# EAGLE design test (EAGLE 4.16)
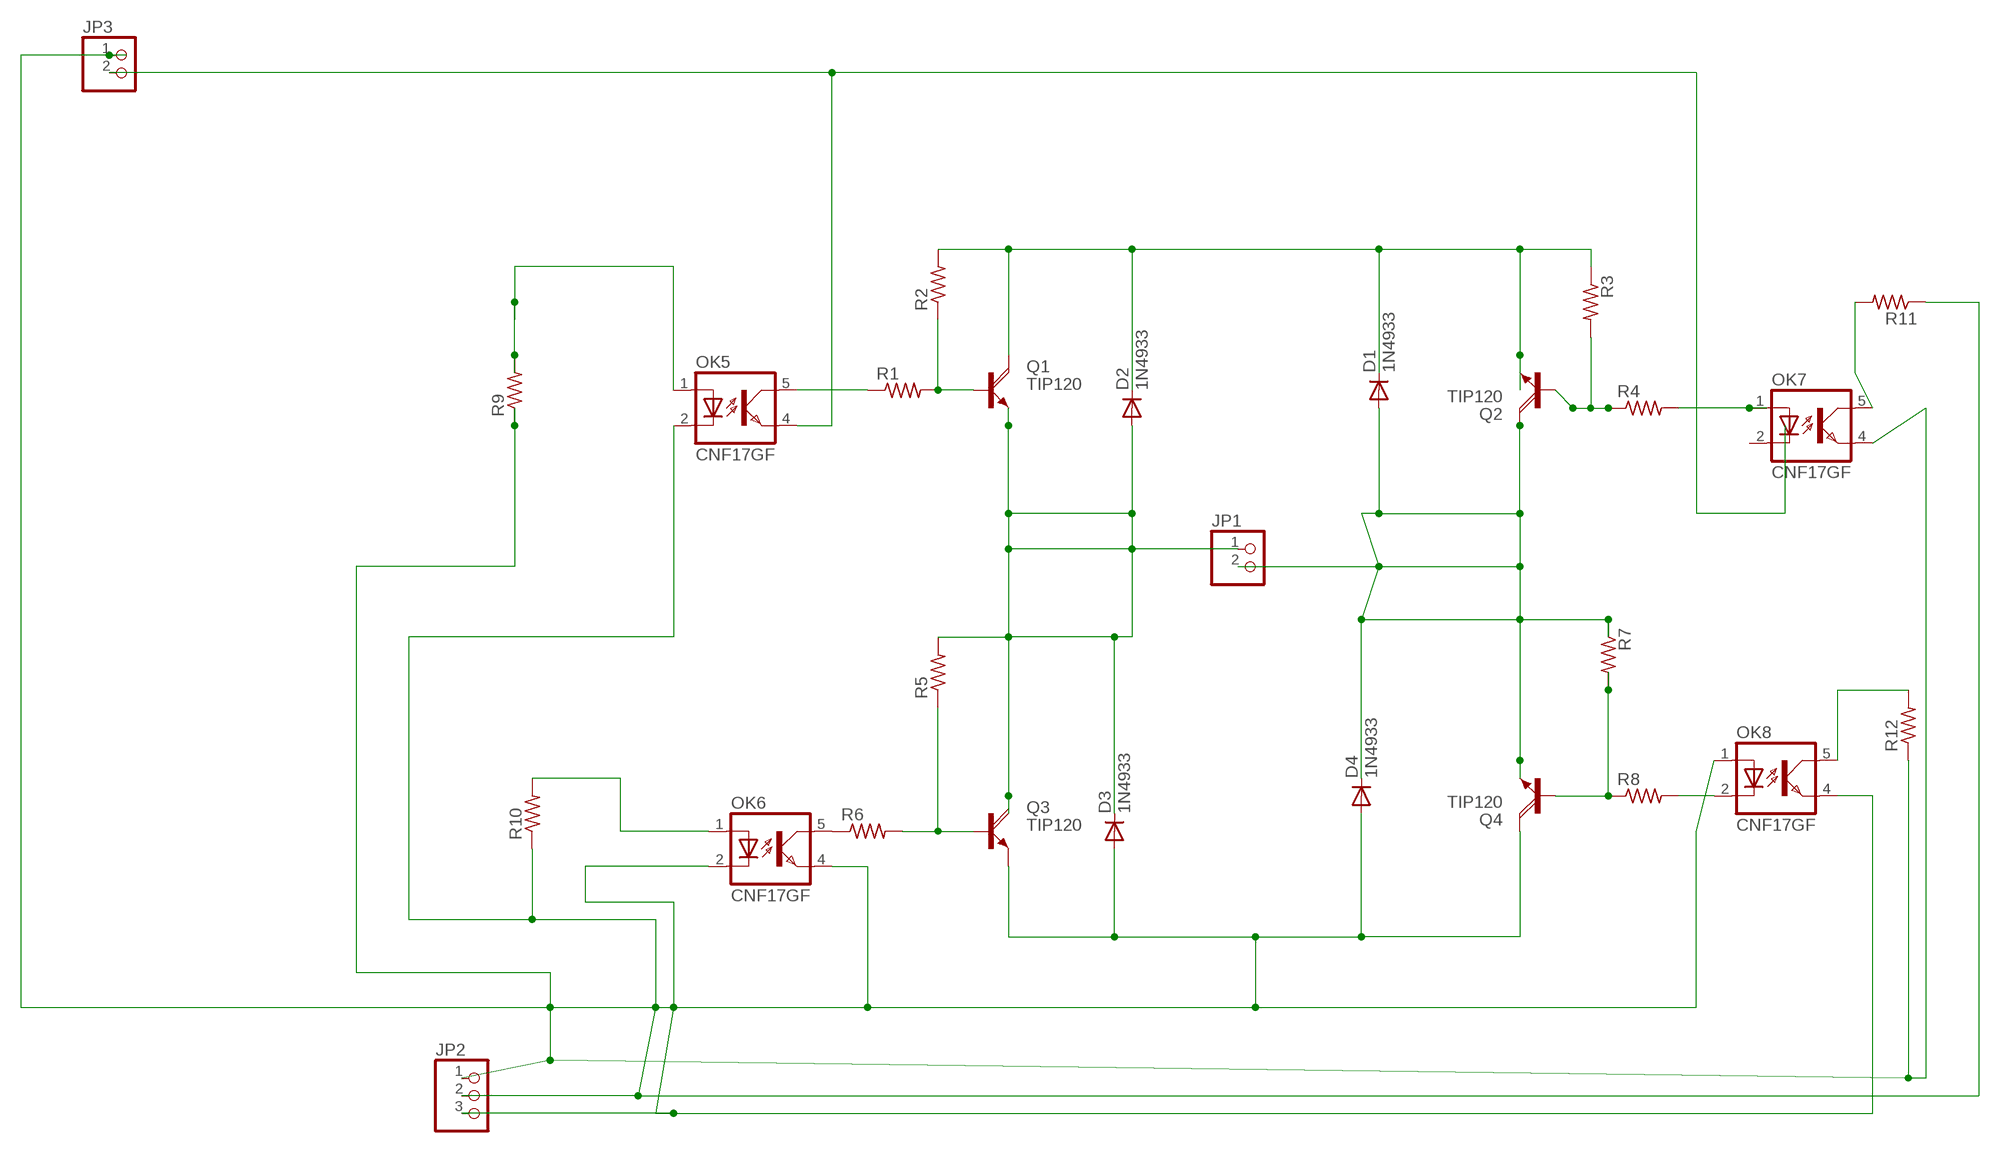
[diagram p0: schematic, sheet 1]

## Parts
D1  1N4933  [DO41-10]
D2  1N4933  [DO41-10]
D3  1N4933  [DO41-10]
D4  1N4933  [DO41-10]
JP1  PINHD-1X2  [1X02]
JP2  PINHD-1X3  [1X03]
JP3  PINHD-1X2  [1X02]
OK5  CNF17GF  [DIL06B]
OK6  CNF17GF  [DIL06B]
OK7  CNF17GF  [DIL06B]
OK8  CNF17GF  [DIL06B]
Q1  TIP120  [TO220AH]
Q2  TIP120  [TO220AH]
Q3  TIP120  [TO220AH]
Q4  TIP120  [TO220AH]
R1  R-US_0204/2V  [0204V]
R2  R-US_0204/2V  [0204V]
R3  R-US_0204/2V  [0204V]
R4  R-US_0204/2V  [0204V]
R5  R-US_0204/2V  [0204V]
R6  R-US_0204/2V  [0204V]
R7  R-US_0204/2V  [0204V]
R8  R-US_0204/2V  [0204V]
R9  R-US_0204/2V  [0204V]
R10  R-US_0204/2V  [0204V]
R11  R-US_0204/2V  [0204V]
R12  R-US_0204/2V  [0204V]

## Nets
N$1: OK5.5(COL) R1.1
N$2: Q1.B R1.2 R2.1
N$3: OK6.5(COL) R6.1
N$4: D1.C D2.C Q1.C Q2.E R2.2 R3.1
N$5: D2.A D3.C JP1.1 Q1.E Q3.C R5.2
N$6: D1.A D4.C JP1.2 Q2.C Q4.E R7.1
N$7: Q2.B R3.2 R4.1
N$8: Q3.B R5.1 R6.2
N$9: OK5.1(A) R9.2
N$10: D3.A D4.A JP2.1 JP2.2 JP2.3 JP3.1 OK5.2(C) OK6.2(C) OK6.4(EMIT) OK7.4(EMIT) OK8.1(A) OK8.4(EMIT) Q3.E Q4.C R9.1 R10.1 R11.1 R12.1
N$11: OK6.1(A) R10.2
N$12: OK7.5(COL) R11.2
N$13: Q4.B R7.2 R8.1
N$14: OK7.1(A) R4.2
N$15: OK8.2(C) R8.2
N$17: JP3.2 OK5.4(EMIT)
N$18: OK8.5(COL) R12.2
Unconnected: OK7.2(C)

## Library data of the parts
D1-D4 = diode:1N4933: DIODE
JP1 JP3 = pinhead:PINHD-1X2: PIN HEADER
JP2 = pinhead:PINHD-1X3: PIN HEADER
OK5-OK8 = optocoupler:CNF17GF: HEWLETT PACKARD OPTO COUPLER
Q1-Q4 = transistor-power:TIP120: NPN DARLINGTON TRANSISTOR
R1-R12 = rcl:R-US_: RESISTOR, American symbol

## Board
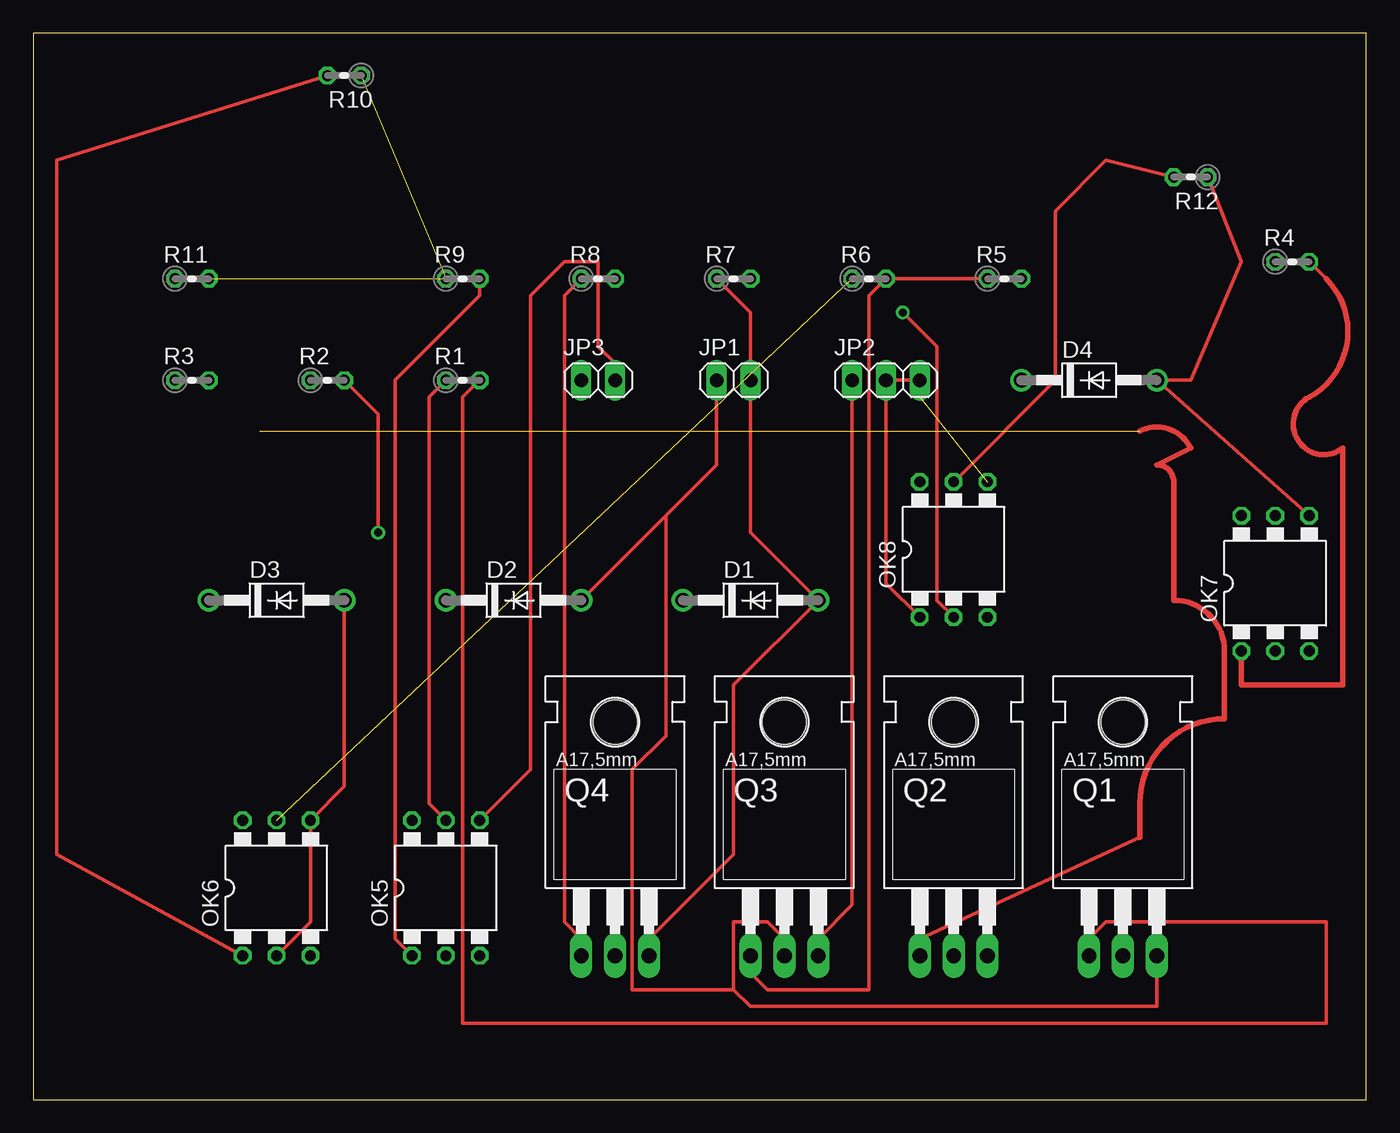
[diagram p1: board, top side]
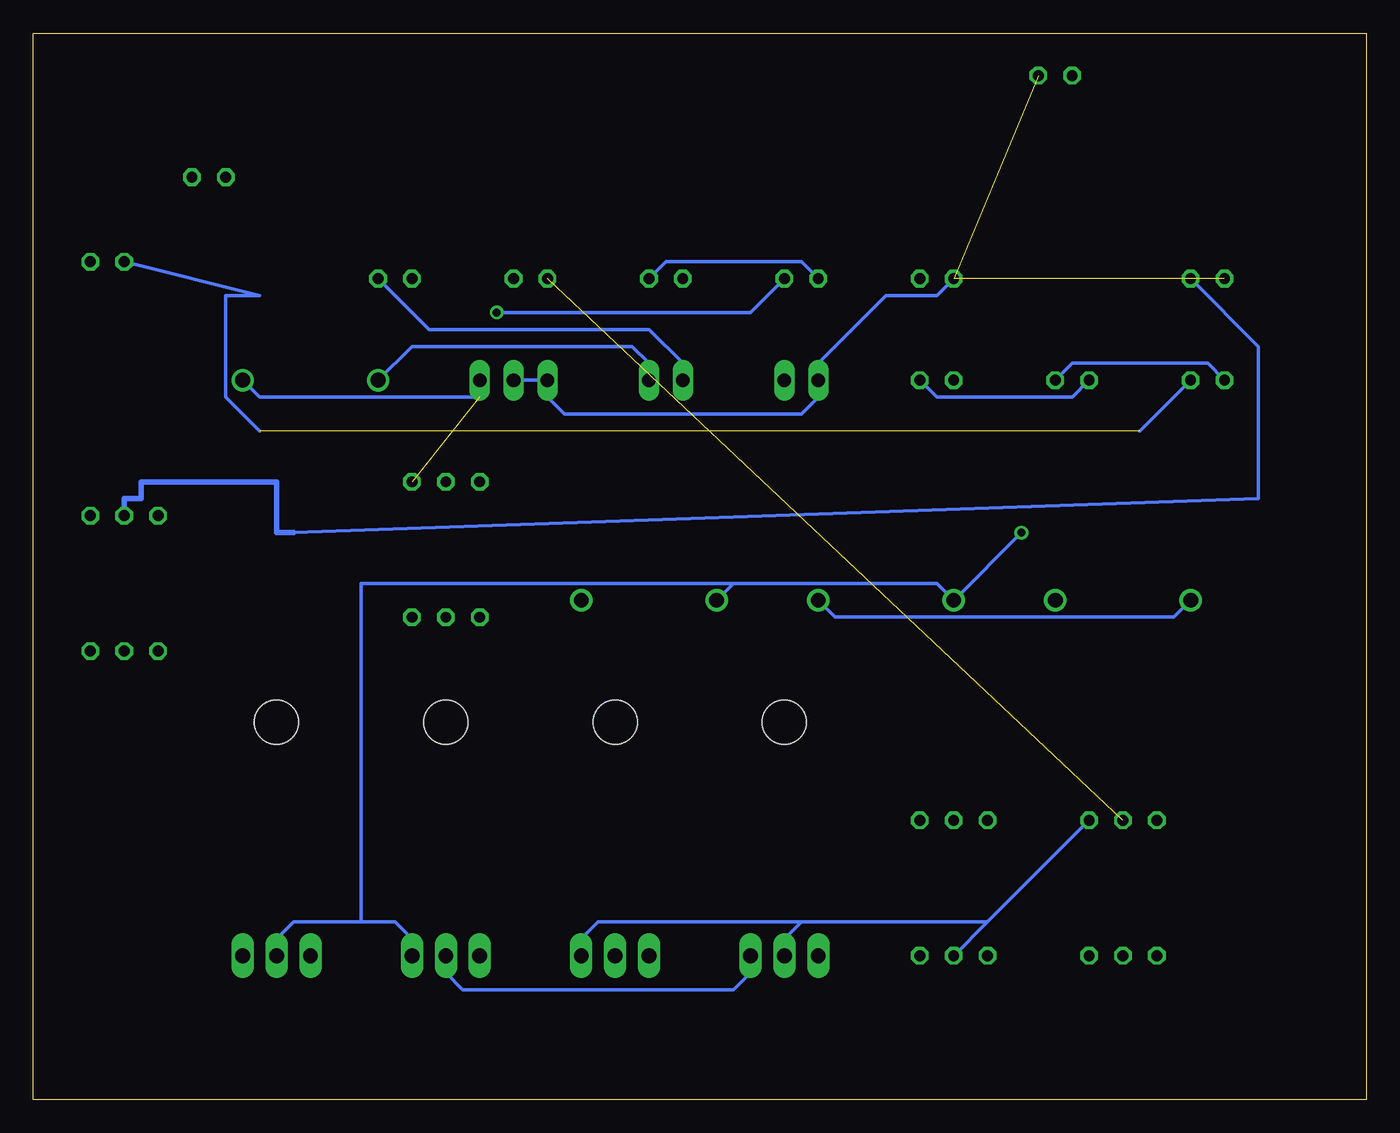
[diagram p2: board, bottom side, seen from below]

Size 100 x 80 mm. Coordinates in mm from the lower left corner, seen from the top.
Outline: 0,0 100,0 100,80 0,80 0,0
Copper layers (1*16): Top 0.035mm / dielectric 1.5mm / Bottom 0.035mm
Design rules "default": minimum track width 10mil, minimum drill 24mil, track to track 8mil, track to pad 8mil, pad to pad 8mil, via to via 8mil, smd to smd 8mil, copper to edge 40mil, drill to drill 8mil, minimum pad ring 10mil, minimum via ring 8mil, stop-mask expansion 4mil, vias tented up to drill 0mil, thermal gap 10mil

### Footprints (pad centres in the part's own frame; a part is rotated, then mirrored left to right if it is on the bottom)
DO41-10 = drill 1.118 round: A 5.08,0; C -5.08,0
1X02 = drill 1.016 long: 1 -1.27,0; 2 1.27,0
1X03 = drill 1.016 long: 1 -2.54,0; 2 0,0; 3 2.54,0
DIL06B = drill 0.813 octagon: 1 -2.54,-5.08; 2 0,-5.08; 3 2.54,-5.08; 4 2.54,5.08; 5 0,5.08; 6 -2.54,5.08
TO220AH = drill 1.118 long: B -2.54,-6.35; C 0,-6.35; E 2.54,-6.35 | hole 3.302: 0,11.176
0204V = drill 0.813 octagon: 1 -1.27,0; 2 1.27,0

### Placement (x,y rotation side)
D1  53.81,37.46 0 top
D2  36.03,37.46 0 top
D3  18.25,37.46 0 top
D4  79.21,53.97 0 top
JP1  52.54,53.97 0 top
JP2  63.97,53.97 0 top
JP3  42.38,53.97 0 top
OK5  30.95,15.87 0 top
OK6  18.25,15.87 0 top
OK7  93.18,38.73 0 top
OK8  69.05,41.27 0 top
Q1  81.75,17.14 0 top
Q2  69.05,17.14 0 top
Q3  56.35,17.14 0 top
Q4  43.65,17.14 0 top
R1  32.22,53.97 0 top
R2  22.06,53.97 0 top
R3  11.9,53.97 0 top
R4  94.45,62.86 0 top
R5  72.86,61.59 0 top
R6  62.7,61.59 0 top
R7  52.54,61.59 0 top
R8  42.38,61.59 0 top
R9  32.22,61.59 0 top
R10  23.33,76.83 180 top
R11  11.9,61.59 0 top
R12  86.83,69.21 180 top

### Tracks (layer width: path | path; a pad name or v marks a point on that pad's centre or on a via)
N$1
  Top 0.254: OK5.5 29.68,22.22 29.68,52.7 R1.1
N$2
  Top 0.254: R1.2 32.22,52.7 32.22,5.71 96.99,5.71 96.99,13.33 80.48,13.33 79.21,12.06 Q1.B
  Bottom 0.254: R2.1 22.06,52.7 32.22,52.7 R1.2
N$3  (1 unrouted)
N$4  (via drill 0.61)
  Top 0.254: R2.2 25.87,51.43 v25.87,42.54
  Bottom 0.254: R3.1 11.9,55.24 22.06,55.24 R2.2 | 75.4,13.33 80.48,13.33 81.75,12.06 Q1.C | 75.4,13.33 72.86,13.33 71.59,12.06 Q2.E | 47.46,38.73 32.22,38.73 D2.C v25.87,42.54 | 47.46,38.73 D1.C | 75.4,13.33 75.4,38.73 47.46,38.73
N$5
  Top 0.254: 52.54,8.25 52.54,13.33 55.08,13.33 56.35,12.06 Q3.C | 52.54,8.25 53.81,6.98 84.29,6.98 Q1.E | 47.46,43.81 51.27,47.62 JP1.1 | D2.A 47.46,43.81 | 52.54,8.25 44.92,8.25 44.92,24.76 47.46,27.3 47.46,43.81
  Bottom 0.254: D3.C 14.44,36.19 39.84,36.19 D2.A | R5.2 70.32,57.78 53.81,57.78 51.27,55.24 JP1.1
N$6
  Top 0.254: R7.1 53.81,59.05 JP1.2 53.81,42.54 D1.A 52.54,31.11 52.54,18.41 46.19,12.06 Q4.E
  Bottom 0.254: Q4.E 46.19,9.52 47.46,8.25 67.78,8.25 69.05,9.52 Q2.C | D4.C 71.59,56.51 55.08,56.51 53.81,55.24 JP1.2
N$7  (1 unrouted)
  Top 0.254: 83.02,19.68 66.51,12.06 Q2.B
  Top 0.406: 83.02,19.68 83.02,22.22 arc-90 89.37,28.57 89.37,33.65 arc90 85.56,37.46 85.56,46.35 arc90 84.29,47.62 86.83,48.89 arc90 83.02,50.16
  Bottom 0.254: 16.98,50.16 R3.2 | 83.02,50.16 85.56,52.7 85.56,60.32 83.02,60.32 R4.1
N$8
  Top 0.254: R5.1 R6.2 62.7,60.32 62.7,8.25 55.08,8.25 53.81,9.52 Q3.B
N$9
  Top 0.254: OK5.1 27.14,12.06 27.14,53.97 33.49,60.32 R9.2
N$10  (3 unrouted)
  Top 0.254: OK6.2 20.79,13.33 OK6.4 23.33,23.49 D3.A | OK8.1 63.97,38.73 JP2.2 JP2.3 | R12.1 90.64,62.86 86.83,53.97 D4.A OK7.4 | Q3.E 58.89,12.06 61.43,14.6 JP2.1
  Bottom 0.254: OK6.4 28.41,13.33 | 28.41,13.33 OK5.2 | 42.38,13.33 43.65,12.06 Q4.C | 28.41,13.33 42.38,13.33 | 42.38,13.33 57.62,13.33 58.89,12.06 Q3.E | R9.1 32.22,60.32 36.03,60.32 41.11,55.24 JP3.1 41.11,52.7 42.38,51.43 60.16,51.43 61.43,52.7 JP2.1 JP2.2 | D4.A 83.02,52.7 66.51,52.7 JP2.3
N$11
  Top 0.254: OK6.1 1.74,18.41 1.74,70.48 R10.2
N$12
  Bottom 0.254: R11.2 8.09,56.51 8.09,45.08 80.48,42.54
  Bottom 0.406: 80.48,42.54 81.75,42.54 81.75,46.35 91.91,46.35 91.91,45.08 93.18,45.08 OK7.5
N$13
  Top 0.254: R8.1 39.84,60.32 39.84,13.33 41.11,12.06 Q4.B
  Bottom 0.254: R8.1 42.38,62.86 52.54,62.86 R7.2
N$14
  Top 0.254: R4.2 96.99,61.59
  Top 0.406: 96.99,61.59 arc-106 95.72,52.7 arc190 98.26,48.89 98.26,31.11 90.64,31.11 OK7.1
N$15  (via drill 0.61)
  Top 0.254: v65.24,59.05 67.78,56.51 67.78,37.46 OK8.2
  Bottom 0.254: R8.2 46.19,59.05 v65.24,59.05
N$17
  Top 0.254: OK5.4 37.3,24.76 37.3,60.32 39.84,62.86 42.38,62.86 42.38,56.51 43.65,55.24 JP3.2
N$18
  Top 0.254: OK8.5 76.67,53.97 76.67,66.67 80.48,70.48 R12.2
